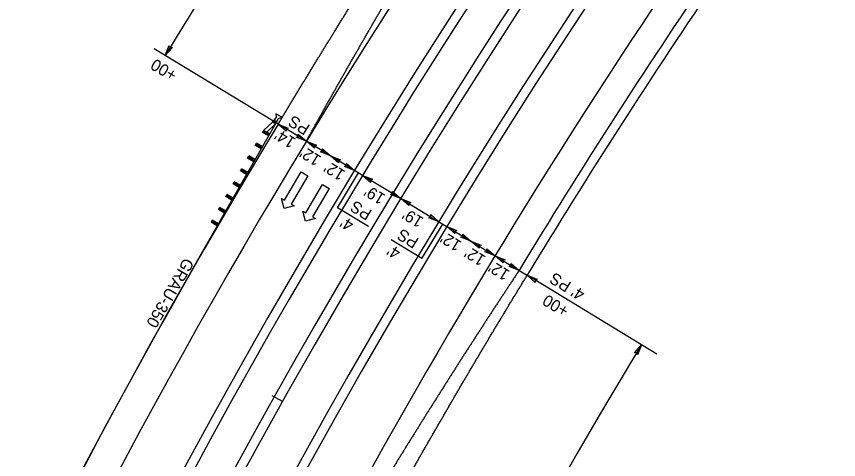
# Model space of a CAD drawing. Extents: x 2389694 to 2405615, y 547005 to 573532.
# Drawn here: x 2400408.7 to 2400758.8, y 569427.6 to 569616.1 of the extents above; entities that cross this region are included whole.
import ezdxf

# ---------------------------------------------------------------- set-up
doc = ezdxf.new("R2010")
doc.units = 0
for name, color, linetype in [('Prop Cable Guiderail Single Face', 7, 'Continuous'), ('Prop Dimension', 7, 'Continuous'), ('Prop Dimension Text', 7, 'Continuous'), ('Prop DSN Text', 7, 'Continuous'), ('Prop EOT', 7, 'Continuous'), ('Prop GRAU M350 Approach CELL', 7, 'Continuous'), ('Prop Guardrail', 7, 'Continuous'), ('Prop Horizontal Alignment', 7, 'Continuous'), ('Prop Horizontal Alignment Tick Small', 7, 'Continuous'), ('Prop Lane Arrow Through CELL', 7, 'Continuous'), ('Prop Lane Lines', 7, 'Continuous')]:
    doc.layers.add(name, color=color, linetype=linetype)

msp = doc.modelspace()

# ---------------------------------------------------------------- linework, layer by layer
at = {"layer": 'Prop Cable Guiderail Single Face'}
msp.add_arc((2403051.7, 568034.46), 2904, 119.41161, 162.0892, dxfattribs=at)
at = {"layer": 'Prop Dimension'}
for p, q in [((2400521.88, 569569.28), (2400467.25, 569602.42)), ((2400532.14, 569563.05), (2400521.88, 569569.28)), ((2400542.4, 569556.83), (2400532.14, 569563.05)), ((2400552.66, 569550.6), (2400542.4, 569556.83)), ((2400545.38, 569534.76), (2400554.37, 569549.57)), ((2400556.08, 569548.53), (2400552.66, 569550.6)), ((2400572.32, 569538.67), (2400556.08, 569548.53)), ((2400572.32, 569538.67), (2400588.56, 569528.82)), ((2400558.54, 569526.78), (2400545.38, 569534.76)), ((2400581.36, 569513.09), (2400590.27, 569527.78)), ((2400588.56, 569528.82), (2400591.98, 569526.74)), ((2400591.98, 569526.74), (2400602.24, 569520.52)), ((2400581.36, 569513.09), (2400568.26, 569521.04)), ((2400602.24, 569520.52), (2400612.5, 569514.3)), ((2400612.5, 569514.3), (2400622.76, 569508.07)), ((2400622.76, 569508.07), (2400626.18, 569506)), ((2400681.41, 569472.49), (2400626.18, 569506))]:
    msp.add_line(p, q, dxfattribs=at)
for points in [[(2400475.06, 569602.94), (2400472.05, 569599.51), (2400473.72, 569603.79), (2400474.11, 569602.88)], [(2400523.61, 569567.32), (2400520.17, 569570.31), (2400524.45, 569568.65), (2400523.54, 569568.27)], [(2400528.69, 569566.05), (2400532.14, 569563.05), (2400527.85, 569564.72), (2400528.76, 569565.1)], [(2400535.58, 569560.06), (2400532.14, 569563.05), (2400536.42, 569561.39), (2400535.51, 569561)], [(2400538.95, 569559.83), (2400542.4, 569556.83), (2400538.11, 569558.49), (2400539.02, 569558.88)], [(2400545.84, 569553.83), (2400542.4, 569556.83), (2400546.68, 569555.17), (2400545.77, 569554.78)], [(2400549.21, 569553.6), (2400552.66, 569550.6), (2400548.37, 569552.27), (2400549.28, 569552.65)], [(2400559.52, 569545.53), (2400556.08, 569548.53), (2400560.36, 569546.87), (2400559.45, 569546.48)], [(2400568.87, 569541.67), (2400572.32, 569538.67), (2400568.04, 569540.34), (2400568.94, 569540.72)], [(2400575.77, 569535.68), (2400572.32, 569538.67), (2400576.6, 569537.01), (2400575.7, 569536.62)], [(2400585.12, 569531.82), (2400588.56, 569528.82), (2400584.28, 569530.48), (2400585.19, 569530.87)], [(2400595.43, 569523.75), (2400591.98, 569526.74), (2400596.27, 569525.08), (2400595.36, 569524.7)], [(2400598.8, 569523.52), (2400602.24, 569520.52), (2400597.96, 569522.18), (2400598.87, 569522.57)], [(2400605.69, 569517.52), (2400602.24, 569520.52), (2400606.53, 569518.86), (2400605.62, 569518.47)], [(2400609.06, 569517.29), (2400612.5, 569514.3), (2400608.22, 569515.96), (2400609.13, 569516.34)], [(2400615.95, 569511.3), (2400612.5, 569514.3), (2400616.79, 569512.63), (2400615.88, 569512.25)], [(2400619.32, 569511.07), (2400622.76, 569508.07), (2400618.48, 569509.73), (2400619.39, 569510.12)], [(2400629.63, 569503), (2400626.18, 569506), (2400630.47, 569504.33), (2400629.56, 569503.95)], [(2400671.91, 569472.99), (2400674.91, 569476.43), (2400673.25, 569472.15), (2400672.86, 569473.06)]]:
    msp.add_lwpolyline(points, close=True, dxfattribs=at)
for radius, start, end in [(3017.28, 142.82813, 148.75528), (2780, 148.7553, 154.68244)]:
    msp.add_arc((2403051.7, 568034.46), radius, start, end, dxfattribs=at)
at = {"layer": 'Prop EOT'}
for radius, start, end in [(2923, 119.41161, 180.94658), (2919, 119.41161, 162.43732), (2881, 119.41161, 165.38993), (2877, 119.41161, 180.94658), (2841, 142.65815, 148.75529), (2837, 142.65815, 148.75529), (2961, 148.75529, 167.84172), (2947, 148.75529, 180.94658)]:
    msp.add_arc((2403051.7, 568034.46), radius, start, end, dxfattribs=at)
for points in [[(2400562.27, 569616.14), (2400562.69, 569616.85), (2400563.1, 569617.56), (2400563.52, 569618.28), (2400563.93, 569618.99), (2400564.35, 569619.7), (2400564.76, 569620.41), (2400565.19, 569621.13), (2400565.6, 569621.84), (2400566.02, 569622.56), (2400566.43, 569623.27), (2400566.85, 569623.98), (2400567.27, 569624.69), (2400567.68, 569625.4), (2400568.1, 569626.11), (2400568.52, 569626.82), (2400568.94, 569627.54), (2400569.35, 569628.25), (2400569.77, 569628.96), (2400570.2, 569629.68), (2400570.61, 569630.39), (2400571.03, 569631.1), (2400571.45, 569631.81), (2400571.87, 569632.52), (2400572.29, 569633.23), (2400572.71, 569633.94), (2400573.13, 569634.65), (2400573.55, 569635.36), (2400573.97, 569636.07), (2400574.39, 569636.78), (2400574.81, 569637.49), (2400575.23, 569638.2), (2400575.66, 569638.91), (2400576.08, 569639.62), (2400576.5, 569640.33), (2400576.92, 569641.04), (2400577.34, 569641.75), (2400577.76, 569642.46), (2400578.19, 569643.17), (2400578.61, 569643.88), (2400579.03, 569644.58), (2400579.45, 569645.29), (2400579.88, 569646), (2400580.3, 569646.71), (2400580.73, 569647.43), (2400581.15, 569648.13), (2400581.57, 569648.84), (2400582, 569649.55), (2400582.42, 569650.26), (2400582.85, 569650.96), (2400583.27, 569651.67), (2400583.7, 569652.38), (2400584.12, 569653.09), (2400584.55, 569653.79), (2400584.97, 569654.5), (2400585.4, 569655.21), (2400585.83, 569655.92), (2400586.25, 569656.63), (2400586.68, 569657.33), (2400587.11, 569658.04), (2400587.53, 569658.75), (2400587.96, 569659.45), (2400588.39, 569660.16), (2400588.81, 569660.86), (2400589.24, 569661.57), (2400589.67, 569662.28), (2400590.1, 569662.98), (2400590.52, 569663.69), (2400590.96, 569664.4), (2400591.39, 569665.11), (2400591.81, 569665.81), (2400592.24, 569666.52), (2400592.67, 569667.22), (2400593.1, 569667.92), (2400593.53, 569668.63)], [(2400520.17, 569570.31), (2400520.59, 569571.02), (2400521.02, 569571.73), (2400521.44, 569572.44), (2400521.87, 569573.15), (2400522.29, 569573.86), (2400522.72, 569574.57), (2400523.15, 569575.29), (2400523.57, 569576), (2400524, 569576.71), (2400524.43, 569577.42), (2400524.85, 569578.12), (2400525.28, 569578.83), (2400525.71, 569579.54), (2400526.13, 569580.25), (2400526.56, 569580.96), (2400526.99, 569581.67), (2400527.42, 569582.37), (2400527.84, 569583.08), (2400528.28, 569583.8), (2400528.7, 569584.51), (2400529.13, 569585.21), (2400529.56, 569585.92), (2400529.99, 569586.63), (2400530.42, 569587.33), (2400530.85, 569588.04), (2400531.28, 569588.75), (2400531.71, 569589.46), (2400532.14, 569590.16), (2400532.57, 569590.87), (2400533, 569591.58), (2400533.43, 569592.29), (2400533.86, 569593), (2400534.3, 569593.7), (2400534.73, 569594.41), (2400535.16, 569595.11), (2400535.59, 569595.82), (2400536.02, 569596.53), (2400536.45, 569597.23), (2400536.88, 569597.94), (2400537.32, 569598.64), (2400537.75, 569599.35), (2400538.18, 569600.05), (2400538.61, 569600.76), (2400539.05, 569601.47), (2400539.49, 569602.17), (2400539.92, 569602.88), (2400540.35, 569603.58), (2400540.79, 569604.29), (2400541.22, 569604.99), (2400541.66, 569605.7), (2400542.09, 569606.4), (2400542.52, 569607.1), (2400542.96, 569607.81), (2400543.39, 569608.51), (2400543.83, 569609.21), (2400544.27, 569609.93), (2400544.71, 569610.63), (2400545.14, 569611.33), (2400545.58, 569612.03), (2400546.01, 569612.74), (2400546.45, 569613.44), (2400546.89, 569614.14), (2400547.32, 569614.85), (2400547.76, 569615.55), (2400548.2, 569616.25), (2400548.63, 569616.95), (2400549.07, 569617.65), (2400549.51, 569618.36), (2400549.95, 569619.07), (2400550.39, 569619.77), (2400550.83, 569620.47), (2400551.27, 569621.17), (2400551.71, 569621.87), (2400552.15, 569622.57)], [(2400532.14, 569563.05), (2400532.54, 569563.77), (2400532.94, 569564.49), (2400533.34, 569565.21), (2400533.74, 569565.93), (2400534.14, 569566.65), (2400534.54, 569567.37), (2400534.94, 569568.1), (2400535.34, 569568.82), (2400535.74, 569569.54), (2400536.14, 569570.26), (2400536.55, 569570.98), (2400536.95, 569571.7), (2400537.35, 569572.42), (2400537.75, 569573.14), (2400538.15, 569573.86), (2400538.56, 569574.58), (2400538.96, 569575.3), (2400539.36, 569576.01), (2400539.77, 569576.74), (2400540.17, 569577.46), (2400540.58, 569578.18), (2400540.98, 569578.9), (2400541.38, 569579.61), (2400541.79, 569580.33), (2400542.19, 569581.05), (2400542.6, 569581.77), (2400543, 569582.49), (2400543.41, 569583.2), (2400543.81, 569583.92), (2400544.22, 569584.64), (2400544.63, 569585.37), (2400545.03, 569586.08), (2400545.44, 569586.8), (2400545.85, 569587.52), (2400546.25, 569588.23), (2400546.66, 569588.95), (2400547.06, 569589.67), (2400547.47, 569590.38), (2400547.88, 569591.1), (2400548.29, 569591.82), (2400548.69, 569592.53), (2400549.1, 569593.25), (2400549.51, 569593.97), (2400549.92, 569594.69), (2400550.33, 569595.41), (2400550.74, 569596.12), (2400551.15, 569596.84), (2400551.56, 569597.55), (2400551.97, 569598.27), (2400552.38, 569598.98), (2400552.79, 569599.7), (2400553.2, 569600.41), (2400553.61, 569601.13), (2400554.02, 569601.84), (2400554.43, 569602.56), (2400554.84, 569603.28), (2400555.25, 569604), (2400555.66, 569604.71), (2400556.08, 569605.43), (2400556.49, 569606.14), (2400556.9, 569606.85), (2400557.31, 569607.57), (2400557.72, 569608.28), (2400558.13, 569609), (2400558.55, 569609.71), (2400558.96, 569610.42), (2400559.37, 569611.14), (2400559.79, 569611.86), (2400560.2, 569612.57), (2400560.62, 569613.29), (2400561.03, 569614), (2400561.45, 569614.71), (2400561.86, 569615.42), (2400562.27, 569616.14)], [(2400622.76, 569508.07), (2400622.32, 569507.41), (2400621.88, 569506.75), (2400621.45, 569506.09), (2400621.01, 569505.42), (2400620.57, 569504.76), (2400620.13, 569504.1), (2400619.69, 569503.43), (2400619.25, 569502.77), (2400618.81, 569502.1), (2400618.37, 569501.44), (2400617.94, 569500.78), (2400617.5, 569500.11), (2400617.06, 569499.45), (2400616.62, 569498.79), (2400616.19, 569498.12), (2400615.75, 569497.46), (2400615.31, 569496.8), (2400614.88, 569496.13), (2400614.44, 569495.46), (2400614, 569494.8), (2400613.57, 569494.13), (2400613.13, 569493.47), (2400612.7, 569492.8), (2400612.26, 569492.14), (2400611.83, 569491.47), (2400611.39, 569490.81), (2400610.96, 569490.14), (2400610.52, 569489.48), (2400610.09, 569488.81), (2400609.65, 569488.15), (2400609.22, 569487.47), (2400608.78, 569486.81), (2400608.35, 569486.14), (2400607.91, 569485.48), (2400607.48, 569484.81), (2400607.05, 569484.14), (2400606.62, 569483.48), (2400606.18, 569482.81), (2400605.75, 569482.14), (2400605.32, 569481.48), (2400604.89, 569480.81), (2400604.46, 569480.14), (2400604.02, 569479.48), (2400603.59, 569478.8), (2400603.16, 569478.13), (2400602.72, 569477.47), (2400602.29, 569476.8), (2400601.86, 569476.13), (2400601.43, 569475.46), (2400601, 569474.79), (2400600.57, 569474.13), (2400600.14, 569473.46), (2400599.71, 569472.79), (2400599.28, 569472.12), (2400598.85, 569471.45), (2400598.42, 569470.78), (2400597.99, 569470.11), (2400597.56, 569469.44), (2400597.13, 569468.77), (2400596.7, 569468.1), (2400596.28, 569467.43), (2400595.85, 569466.76), (2400595.42, 569466.09), (2400594.99, 569465.42), (2400594.56, 569464.75), (2400594.14, 569464.08), (2400593.71, 569463.41), (2400593.28, 569462.73), (2400592.85, 569462.06), (2400592.42, 569461.39), (2400592, 569460.72), (2400591.57, 569460.05), (2400591.14, 569459.38), (2400590.72, 569458.71)], [(2400593.91, 569452.01), (2400594.34, 569452.75), (2400594.77, 569453.48), (2400595.2, 569454.22), (2400595.63, 569454.95), (2400596.06, 569455.69), (2400596.49, 569456.42), (2400596.92, 569457.15), (2400597.34, 569457.88), (2400597.77, 569458.62), (2400598.2, 569459.35), (2400598.63, 569460.08), (2400599.07, 569460.82), (2400599.5, 569461.55), (2400599.93, 569462.28), (2400600.36, 569463.02), (2400600.79, 569463.74), (2400601.22, 569464.48), (2400601.65, 569465.21), (2400602.08, 569465.94), (2400602.52, 569466.68), (2400602.95, 569467.41), (2400603.38, 569468.14), (2400603.81, 569468.86), (2400604.25, 569469.6), (2400604.68, 569470.33), (2400605.11, 569471.06), (2400605.55, 569471.79), (2400605.98, 569472.53), (2400606.42, 569473.26), (2400606.85, 569473.99), (2400607.28, 569474.71), (2400607.72, 569475.44), (2400608.15, 569476.17), (2400608.59, 569476.91), (2400609.03, 569477.64), (2400609.46, 569478.37), (2400609.9, 569479.1), (2400610.34, 569479.83), (2400610.77, 569480.55), (2400611.21, 569481.28), (2400611.64, 569482.01), (2400612.08, 569482.74), (2400612.52, 569483.47), (2400612.96, 569484.2), (2400613.4, 569484.93), (2400613.83, 569485.66), (2400614.27, 569486.38), (2400614.71, 569487.11), (2400615.15, 569487.84), (2400615.59, 569488.57), (2400616.03, 569489.3), (2400616.47, 569490.02), (2400616.91, 569490.75), (2400617.35, 569491.48), (2400617.78, 569492.2), (2400618.22, 569492.93), (2400618.66, 569493.66), (2400619.1, 569494.39), (2400619.55, 569495.11), (2400619.99, 569495.84), (2400620.43, 569496.57), (2400620.87, 569497.3), (2400621.31, 569498.01), (2400621.75, 569498.74), (2400622.19, 569499.47), (2400622.64, 569500.19), (2400623.08, 569500.92), (2400623.52, 569501.65), (2400623.97, 569502.37), (2400624.41, 569503.1), (2400624.85, 569503.82), (2400625.29, 569504.54), (2400626.18, 569506)], [(2400590.72, 569458.71), (2400590.29, 569458.04), (2400589.87, 569457.36), (2400589.44, 569456.69), (2400589.02, 569456.02), (2400588.59, 569455.35), (2400588.17, 569454.68), (2400587.74, 569454), (2400587.31, 569453.33), (2400586.89, 569452.65), (2400586.46, 569451.98), (2400586.04, 569451.31), (2400585.62, 569450.64), (2400585.19, 569449.96), (2400584.77, 569449.29), (2400584.35, 569448.62), (2400583.92, 569447.94), (2400583.5, 569447.27), (2400583.08, 569446.6), (2400582.65, 569445.92), (2400582.23, 569445.24), (2400581.81, 569444.57), (2400581.38, 569443.89), (2400580.96, 569443.22), (2400580.54, 569442.55), (2400580.12, 569441.87), (2400579.7, 569441.2), (2400579.28, 569440.52), (2400578.86, 569439.85), (2400578.44, 569439.17), (2400578.02, 569438.5), (2400577.59, 569437.82), (2400577.17, 569437.14), (2400576.75, 569436.47), (2400576.33, 569435.79), (2400575.91, 569435.11), (2400575.49, 569434.44), (2400575.07, 569433.76), (2400574.65, 569433.09), (2400574.23, 569432.41), (2400573.82, 569431.74), (2400573.4, 569431.06), (2400572.98, 569430.38), (2400572.56, 569429.71), (2400572.14, 569429.02), (2400571.72, 569428.34), (2400571.3, 569427.67), (2400570.89, 569426.99), (2400570.47, 569426.31), (2400570.05, 569425.64), (2400569.64, 569424.96), (2400569.22, 569424.28), (2400568.8, 569423.6), (2400568.39, 569422.93), (2400567.97, 569422.25), (2400567.55, 569421.57), (2400567.13, 569420.88), (2400566.72, 569420.21), (2400566.3, 569419.53), (2400565.89, 569418.85), (2400565.47, 569418.17), (2400565.06, 569417.49), (2400564.64, 569416.81), (2400564.23, 569416.13), (2400563.81, 569415.45), (2400563.4, 569414.78), (2400562.99, 569414.1), (2400562.57, 569413.42), (2400562.16, 569412.73), (2400561.74, 569412.05), (2400561.33, 569411.37), (2400560.92, 569410.69), (2400560.5, 569410.01), (2400560.09, 569409.33), (2400559.68, 569408.65)], [(2400562.85, 569397.33), (2400563.26, 569398.07), (2400563.67, 569398.81), (2400564.08, 569399.55), (2400564.49, 569400.3), (2400564.91, 569401.04), (2400565.32, 569401.78), (2400565.73, 569402.53), (2400566.15, 569403.27), (2400566.56, 569404.02), (2400566.97, 569404.76), (2400567.38, 569405.49), (2400567.8, 569406.24), (2400568.21, 569406.98), (2400568.63, 569407.72), (2400569.05, 569408.47), (2400569.46, 569409.21), (2400569.88, 569409.95), (2400570.29, 569410.69), (2400570.7, 569411.43), (2400571.12, 569412.17), (2400571.54, 569412.91), (2400571.96, 569413.66), (2400572.37, 569414.4), (2400572.79, 569415.14), (2400573.21, 569415.88), (2400573.63, 569416.62), (2400574.04, 569417.36), (2400574.46, 569418.1), (2400574.88, 569418.84), (2400575.29, 569419.58), (2400575.71, 569420.32), (2400576.13, 569421.06), (2400576.55, 569421.8), (2400576.97, 569422.54), (2400577.39, 569423.27), (2400577.81, 569424.01), (2400578.23, 569424.75), (2400578.65, 569425.49), (2400579.07, 569426.23), (2400579.49, 569426.97), (2400579.91, 569427.71), (2400580.33, 569428.45), (2400580.75, 569429.18), (2400581.17, 569429.92), (2400581.59, 569430.66), (2400582.02, 569431.4), (2400582.44, 569432.14), (2400582.86, 569432.88), (2400583.28, 569433.62), (2400583.7, 569434.35), (2400584.13, 569435.09), (2400584.55, 569435.83), (2400584.97, 569436.56), (2400585.4, 569437.3), (2400585.82, 569438.04), (2400586.25, 569438.78), (2400586.67, 569439.52), (2400587.09, 569440.24), (2400587.52, 569440.98), (2400587.94, 569441.72), (2400588.37, 569442.46), (2400588.79, 569443.19), (2400589.22, 569443.93), (2400589.65, 569444.67), (2400590.07, 569445.4), (2400590.49, 569446.13), (2400590.92, 569446.87), (2400591.35, 569447.6), (2400591.78, 569448.34), (2400592.2, 569449.08), (2400592.63, 569449.81), (2400593.06, 569450.55), (2400593.49, 569451.28), (2400593.91, 569452.01)]]:
    msp.add_spline(points, degree=3, dxfattribs=at)
at = {"layer": 'Prop GRAU M350 Approach CELL'}
for p, q in [((2400519.24, 569573.28), (2400518.19, 569571.52)), ((2400521.63, 569573.22), (2400519.11, 569574.73)), ((2400519.11, 569574.73), (2400519.24, 569573.28)), ((2400519.24, 569570.89), (2400520.29, 569572.65)), ((2400520.29, 569572.65), (2400521.63, 569573.22)), ((2400494.4, 569527.45), (2400519.29, 569570.83)), ((2400513.95, 569567.67), (2400517.74, 569571.14)), ((2400515.27, 569566.91), (2400519.04, 569570.4)), ((2400517.74, 569571.14), (2400518.24, 569572.01)), ((2400517.74, 569571.14), (2400517.99, 569571.58)), ((2400519.54, 569571.26), (2400517.74, 569571.14)), ((2400519.04, 569570.4), (2400517.74, 569571.14)), ((2400518.19, 569571.52), (2400518.72, 569571.21)), ((2400519.54, 569571.26), (2400518.24, 569572.01)), ((2400518.24, 569572.01), (2400519.04, 569570.4)), ((2400518.72, 569571.21), (2400519.24, 569570.89)), ((2400513.45, 569566.8), (2400513.95, 569567.67)), ((2400515.27, 569566.91), (2400513.45, 569566.8)), ((2400516.1, 569565.28), (2400513.45, 569566.8)), ((2400516.6, 569566.14), (2400513.95, 569567.67)), ((2400513.95, 569567.67), (2400514.78, 569566.04)), ((2400514.78, 569566.04), (2400515.27, 569566.91)), ((2400514.78, 569566.04), (2400516.6, 569566.14)), ((2400516.1, 569565.28), (2400515.27, 569566.91)), ((2400510.37, 569561.3), (2400510.87, 569562.17)), ((2400513.47, 569560.68), (2400510.87, 569562.17)), ((2400510.87, 569562.17), (2400511.67, 569560.56)), ((2400512.17, 569561.43), (2400510.37, 569561.3)), ((2400512.97, 569559.81), (2400510.37, 569561.3)), ((2400511.67, 569560.56), (2400512.17, 569561.43)), ((2400511.67, 569560.56), (2400513.47, 569560.68)), ((2400512.97, 569559.81), (2400512.17, 569561.43)), ((2400507.11, 569555.91), (2400507.61, 569556.77)), ((2400508.97, 569555.99), (2400507.11, 569555.91)), ((2400509.83, 569554.35), (2400507.11, 569555.91)), ((2400510.33, 569555.21), (2400507.61, 569556.77)), ((2400507.61, 569556.77), (2400508.47, 569555.13)), ((2400508.47, 569555.13), (2400508.97, 569555.99)), ((2400508.47, 569555.13), (2400510.33, 569555.21)), ((2400509.83, 569554.35), (2400508.97, 569555.99)), ((2400504.06, 569550.39), (2400504.56, 569551.26)), ((2400507.19, 569549.75), (2400504.56, 569551.26)), ((2400504.56, 569551.26), (2400505.38, 569549.64)), ((2400505.88, 569550.5), (2400504.06, 569550.39)), ((2400506.7, 569548.88), (2400504.06, 569550.39)), ((2400505.38, 569549.64), (2400505.88, 569550.5)), ((2400505.38, 569549.64), (2400507.19, 569549.75)), ((2400506.7, 569548.88), (2400505.88, 569550.5)), ((2400506.7, 569548.88), (2400507.19, 569549.75)), ((2400500.92, 569544.93), (2400501.42, 569545.8)), ((2400502.74, 569545.04), (2400500.92, 569544.93)), ((2400503.56, 569543.41), (2400500.92, 569544.93)), ((2400504.06, 569544.28), (2400501.42, 569545.8)), ((2400501.42, 569545.8), (2400502.24, 569544.17)), ((2400502.24, 569544.17), (2400502.74, 569545.04)), ((2400502.24, 569544.17), (2400504.06, 569544.28)), ((2400503.56, 569543.41), (2400502.74, 569545.04)), ((2400497.78, 569539.47), (2400498.28, 569540.34)), ((2400499.6, 569539.58), (2400497.78, 569539.47)), ((2400500.43, 569537.95), (2400497.78, 569539.47)), ((2400500.92, 569538.82), (2400498.28, 569540.34)), ((2400498.28, 569540.34), (2400499.1, 569538.71)), ((2400499.1, 569538.71), (2400499.6, 569539.58)), ((2400499.1, 569538.71), (2400500.92, 569538.82)), ((2400500.43, 569537.95), (2400499.6, 569539.58)), ((2400494.69, 569533.98), (2400495.19, 569534.84)), ((2400496.49, 569534.1), (2400494.69, 569533.98)), ((2400497.29, 569532.48), (2400494.69, 569533.98)), ((2400497.79, 569533.35), (2400495.19, 569534.84)), ((2400495.19, 569534.84), (2400495.99, 569533.23)), ((2400495.99, 569533.23), (2400496.49, 569534.1)), ((2400497.79, 569533.35), (2400496.49, 569534.1)), ((2400496.49, 569534.1), (2400497.29, 569532.48)), ((2400495.99, 569533.23), (2400497.79, 569533.35)), ((2400497.29, 569532.48), (2400497.79, 569533.35)), ((2400492.09, 569529.43), (2400491.57, 569528.57)), ((2400491.57, 569528.57), (2400493.37, 569528.65)), ((2400494.14, 569527.02), (2400491.57, 569528.57)), ((2400494.66, 569527.88), (2400492.09, 569529.43)), ((2400492.86, 569527.8), (2400492.09, 569529.43)), ((2400492.86, 569527.8), (2400493.37, 569528.65)), ((2400494.66, 569527.88), (2400492.86, 569527.8)), ((2400493.37, 569528.65), (2400494.14, 569527.02)), ((2400494.14, 569527.02), (2400494.66, 569527.88))]:
    msp.add_line(p, q, dxfattribs=at)
at = {"layer": 'Prop Guardrail'}
for p, q in [((2400494.14, 569527.02), (2400474.14, 569492.07)), ((2400474.14, 569492.07), (2400446.31, 569441.34)), ((2400446.31, 569441.34), (2400415.2, 569382.52))]:
    msp.add_line(p, q, dxfattribs=at)
at = {"layer": 'Prop Horizontal Alignment'}
msp.add_arc((2403051.7, 568034.46), 2900, 119.41161, 180.94658, dxfattribs=at)
at = {"layer": 'Prop Horizontal Alignment Tick Small'}
for p, q in [((2400572.32, 569538.67), (2400568.04, 569541.27)), ((2400521.93, 569452.3), (2400517.57, 569454.74))]:
    msp.add_line(p, q, dxfattribs=at)
at = {"layer": 'Prop Lane Arrow Through CELL'}
for p, q in [((2400522.8, 569537.94), (2400529.94, 569549.98)), ((2400532.78, 569548.3), (2400525.64, 569536.26)), ((2400529.94, 569549.98), (2400532.78, 569548.3)), ((2400531.87, 569532.6), (2400539.01, 569544.64)), ((2400539.01, 569544.64), (2400541.85, 569542.96)), ((2400541.85, 569542.96), (2400534.71, 569530.92)), ((2400522.66, 569534.36), (2400521.51, 569538.7)), ((2400521.51, 569538.7), (2400522.8, 569537.94)), ((2400526.93, 569535.49), (2400522.66, 569534.36)), ((2400525.64, 569536.26), (2400526.93, 569535.49)), ((2400531.73, 569529.02), (2400530.58, 569533.36)), ((2400530.58, 569533.36), (2400531.87, 569532.6)), ((2400536, 569530.15), (2400531.73, 569529.02)), ((2400534.71, 569530.92), (2400536, 569530.15))]:
    msp.add_line(p, q, dxfattribs=at)
at = {"layer": 'Prop Lane Lines'}
for radius, start, end in [(2947, 129.29029, 148.75528), (2853, 131.16509, 154.68244)]:
    msp.add_arc((2403051.7, 568034.46), radius, start, end, dxfattribs=at)

# ---------------------------------------------------------------- texts
at = {"layer": 'Prop Dimension Text'}
for s, rotation, p in [('+00', 149.2979, (2400477.57, 569592.61)), ('PS', 148.1538, (2400534.07, 569569.6)), ("14'", 148.1538, (2400528.06, 569563.92)), ("12'", 148.1538, (2400538.83, 569556.37)), ("12'", 148.1538, (2400549.09, 569550.15)), ("19'", 148.7552, (2400566.24, 569540.02)), ('PS', 148.1538, (2400560.48, 569533.33)), ("4'", 148.1538, (2400552.79, 569528.68)), ("19'", 148.7552, (2400582.48, 569530.17)), ('PS', 148.1538, (2400580.45, 569521.37)), ("12'", 148.1538, (2400598.68, 569520.06)), ("4'", 148.1538, (2400572.77, 569516.71)), ("12'", 148.1538, (2400608.94, 569513.84)), ("12'", 148.1538, (2400619.2, 569507.62)), ("4' PS", 148.1538, (2400651.22, 569499.14)), ('+00', 149.2979, (2400644.47, 569492.31))]:
    msp.add_text(s, height=5, rotation=rotation, dxfattribs=at).set_placement(p)
at = {"layer": 'Prop DSN Text'}
msp.add_text('GRAU-350', height=5, rotation=239.6676, dxfattribs=at).set_placement((2400480.28, 569513.81))

doc.saveas('drawing.dxf')
